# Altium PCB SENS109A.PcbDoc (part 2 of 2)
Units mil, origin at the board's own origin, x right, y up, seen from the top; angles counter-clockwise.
Board outline 2760 x 2518.85 mil, 4 copper layers (Top Layer, Signal Layer 1, Signal Layer 2, Bottom Layer), stack 62.2 mil thick; 49 components, 21 nets, 113 pads, 294 vias.
Unrouted connection lines stored in the file: 4.
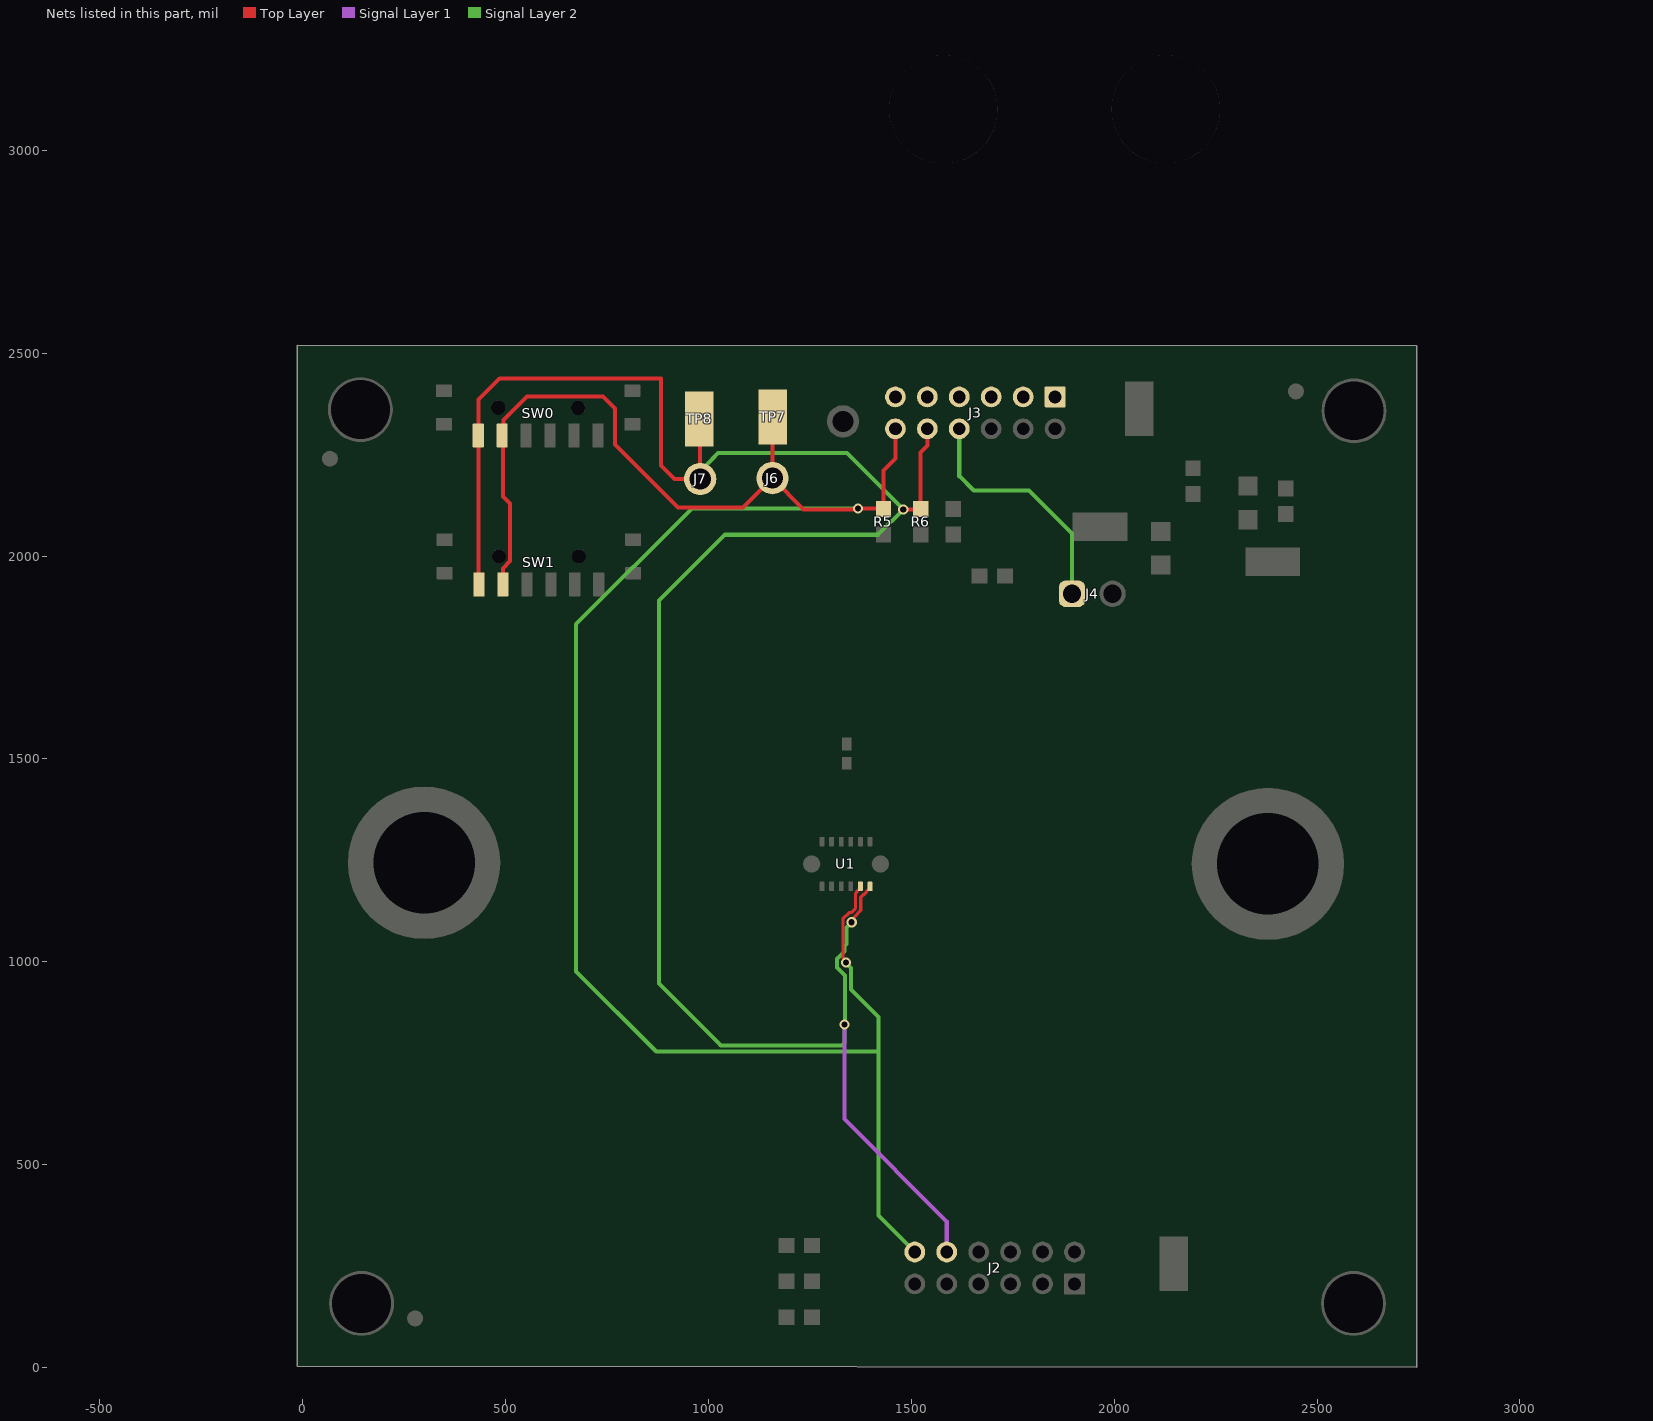
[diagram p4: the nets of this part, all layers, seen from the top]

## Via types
v1: diameter 25, hole 15, Top Layer to Bottom Layer, tented both sides, 193 vias
v2: diameter 18, hole 8, Top Layer to Bottom Layer, tented both sides, 97 vias
v3: diameter 25, hole 15, Top Layer to Bottom Layer, 4 vias

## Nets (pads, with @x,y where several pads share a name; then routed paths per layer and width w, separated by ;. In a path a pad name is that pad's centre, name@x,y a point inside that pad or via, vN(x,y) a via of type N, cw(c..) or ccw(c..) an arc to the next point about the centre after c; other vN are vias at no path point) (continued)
PD2_IN: J3.8 J4.1 | length 601.6
  Signal Layer 2 w10: J3.8@1618.18,2313.64 1618.18,2196.82 1653.88,2161.12 1790.31,2161.12 1896,2055.44 J4.1@1896,1907
PN4: J2.12 J3.12 J6.1 R5.1 SW0.5 SW1.5 TP7.1 U1.5 | length 5464.6
  Top Layer w8: v3(1339,998.12) 1339,1002.72 1331.5,1010.22 1331.5,1106.32 1346.54,1121.37 1351.54,1121.37 1362.62,1132.44 1362.62,1168.51 1365.72,1171.61 1365.72,1173.51 1370.4,1178.19 1372.53,1178.19 1373.53,1179.19 U1.5@1373.53,1185.1
  Top Layer w10: SW1.5@493,1929.69 SW1.5@493.42,1930.1 493.42,1969.65 511.29,1987.52 511.29,2129.11 493.42,2146.98 493.42,2295.1 SW0.5@491.42,2297.1 494.77,2300.46 494.77,2335.77 552.72,2393.72 740.28,2393.72 770,2364 770,2275 924.88,2120.12 1085.66,2120.12 J6.1@1157.66,2192.12 ; TP7.1@1158.66,2343.12 1157.66,2342.12 J6.1@1157.66,2192.12 ; U1.5@1373.53,1185.1 U1.5@1374.43,1186 ; R5.1@1431.17,2115.12 1429.17,2117.12 v1(1368.66,2117.12) 1366.66,2115.12 1234.66,2115.12 J6.1@1157.66,2192.12 ; R5.1@1431.17,2115.62 1431.17,2210.84 1441.36,2221.04 1460.66,2240.34 1460.66,2309.34 J3.12@1460.7,2309.38
  Signal Layer 2 w10: J6.1@1155.56,2190.02 J6.1@1157.66,2192.12 ; v3(1339,998.12) 1339,997.47 1351.7,984.77 1351.7,931.42 1372.25,910.87 1372.41,910.87 1419,864.29 1419,779.12 ; v1(1368.66,2117.12) 959.12,2117.12 674,1832 674,976.44 871.32,779.12 1419,779.12 ; J2.12@1508.52,284.74 1419,374.26 1419,779.12
PN5: J2.10 J3.10 J7.1 R6.1 SW0.6 SW1.6 TP8.1 U1.6 | length 5571.9
  Top Layer w8: v1(1353,1097.42) 1353,1102.02 1358.82,1107.83 1358.82,1110.25 1375.62,1127.06 1375.62,1159.48 1381.34,1165.19 1382.92,1165.19 1389.34,1171.61 1389.34,1173.19 1394.34,1178.19 1396.15,1178.19 1397.15,1179.19 U1.6@1397.15,1185.1
  Top Layer w10: SW1.6@433.36,1914.1 433.36,2386 485.51,2438.15 883,2438.15 883,2223 915.88,2190.12 J7.1@979.66,2190.12 979.66,2336.12 TP8.1@977.66,2338.12 977.66,2353.12 TP8.1@947.66,2383.12 ; U1.6@1397.15,1185.1 U1.6@1398.06,1186 ; v1(1480.17,2115.12) R6.1@1521.67,2115.12 ; R6.1@1523.17,2116.62 1522.17,2117.62 1522.17,2255.63 1539.44,2272.9 J3.10@1539.44,2313.64
  Signal Layer 1 w10: v3(1335,845) 1335,612.12 1587.26,359.86 J2.10@1587.26,284.74
  Signal Layer 2 w10: J7.1@979.66,2190.12 979.66,2208.94 1008.41,2237.69 1008.41,2238.68 1023.86,2254.12 1341.17,2254.12 v1(1480.17,2115.12) 1417.67,2052.63 1040.5,2052.63 878,1890.12 878,946.45 1030.33,794.12 1329.14,794.12 1335,799.98 v3(1335,845) ; v3@1336.7,846.7 1336.7,965.83 1316.5,986.03 1316.5,1007.44 1335,1025.94 1335,1038.92 1340.09,1044.01 1340.09,1084.06 1353,1096.97 v1(1353,1097.42)
PP0: J3.9
PP1: J3.11
PQ0: J3.3
PQ1: J3.1
PQ2: J3.5
PQ3: J3.7
pads on no net: FID1.1 FID2.1 FID3.1 H1.0 H2.0 H3.0 H4.0 H5.0 J2.1 J2.3 J2.5 J2.7 J2.9 J2.11 MP5. MP6. R745A.1 R745A.2 R745B.1 R745B.2 R746.1 R746.2 SW0. SW1.

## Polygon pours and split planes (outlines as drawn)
IS+ on Bottom Layer "BOTTOM_LAYER_IS+_P032" (solid, remove dead copper, pour order 32): 61,1820.12 1335,1820.12 1335,662.12 61,662.12
IS- on Bottom Layer "BOTTOM_LAYER_IS-_P034" (solid, remove dead copper, pour order 34): 1343,1820.12 2617,1820.12 2617,662.12 1343,662.12
IS- on Top Layer "TOP_LAYER_IS-_P028" (solid, remove dead copper, pour order 28): 1343,1820.12 2617,1820.12 2617,662.12 1343,662.12
GND on Top Layer "TOP_LAYER_GND_P030" (solid, remove dead copper, pour order 30): 1253.66,2478.12 1253.66,2161.12 2136.66,2161.12 2136.66,2478.12
IS+ on Top Layer "TOP_LAYER_IS+_P026" (solid, pour order 26): 61,1820.12 1335,1820.12 1335,662.12 61,662.12
IS+ on Signal Layer 1 "SIGNAL_LAYER_1_IS+_P036" (solid, remove dead copper, pour order 36): 61,1820.12 1335,1820.12 1335,662.12 61,662.12
IS- on Signal Layer 1 "SIGNAL_LAYER_1_IS-_P040" (solid, remove dead copper, pour order 40): 1343,1820.12 2617,1820.12 2617,662.12 1343,662.12
IS+ on Signal Layer 2 "SIGNAL_LAYER_2_IS+_P038" (solid, remove dead copper, pour order 38): 61,1820.12 1335,1820.12 1335,662.12 61,662.12
IS- on Signal Layer 2 "SIGNAL_LAYER_2_IS-_P044" (solid, remove dead copper, pour order 44): 1343,1820.12 2617,1820.12 2617,662.12 1343,662.12

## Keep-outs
Keep-Out Layer:
  text ".Layer_Name" at 263,-990.37 h60

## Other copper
Top Layer:
  text ".Layer_Name" at 263,-990.37 h60
Bottom Layer:
  text ".Layer_Name" at 263,-990.37 h60

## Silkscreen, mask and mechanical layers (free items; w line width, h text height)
Top Overlay:
  circle w8: c404,1590 r11.4
  circle w8: c2474,723 r11.4
  lines w10: 46,1835.12 118,1835.12 ; 47,681.62 47,748.62 ; 47,790.62 47,857.62 ; 47,899.62 47,966.62 ; 47,1007.62 47,1074.62 ; 47,1116.62 47,1183.62 ; 47,1225.62 47,1292.62 ; 47,1332.62 47,1399.62 ; 47,1441.62 47,1508.62 ; 47,1550.62 47,1617.62 ; 47,1658.62 47,1725.62 ; 47,1767.62 47,1834.62 ; 48,645.12 120,645.12 ; 156,1835.12 228,1835.12 ; 158,645.12 230,645.12 ; 264,1835.12 336,1835.12 ; 266,645.12 338,645.12 ; 348,350 1306,350 ; 374,1835.12 446,1835.12 ; 376,645.12 448,645.12 ; 483,1835.12 555,1835.12 ; 485,645.12 557,645.12 ; 593,1835.12 665,1835.12 ; 595,645.12 667,645.12 ; 705,1835.12 777,1835.12 ; 707,645.12 779,645.12 ; 815,1835.12 887,1835.12 ; 817,645.12 889,645.12 ; 826.5,72 826.5,442 ; 924,1835.12 996,1835.12 ; 926,645.12 998,645.12 ; 1034,1835.12 1106,1835.12 ; 1036,645.12 1108,645.12 ; 1138,72 1138,439 ; 1142,1835.12 1214,1835.12 ; 1144,645.12 1216,645.12 ; 1252,1835.12 1324,1835.12 ; 1254,645.12 1326,645.12 ; 1361,1835.12 1433,1835.12 ; 1363,645.12 1435,645.12 ; 1471,1835.12 1543,1835.12 ; 1473,645.12 1545,645.12 ; 1581,1835.12 1653,1835.12 ; 1583,645.12 1655,645.12 ; 1691,1835.12 1763,1835.12 ; 1693,645.12 1765,645.12 ; 1800,1835.12 1872,1835.12 ; 1802,645.12 1874,645.12 ; 1910,1835.12 1982,1835.12 ; 1912,645.12 1984,645.12 ; 2018,1835.12 2090,1835.12 ; 2020,645.12 2092,645.12 ; 2128,1835.12 2200,1835.12 ; 2130,645.12 2202,645.12 ; 2237,1835.12 2309,1835.12 ; 2239,645.12 2311,645.12 ; 2347,1835.12 2419,1835.12 ; 2349,645.12 2421,645.12 ; 2456,1835.12 2528,1835.12 ; 2458,645.12 2530,645.12 ; 2566,1835.12 2638,1835.12 ; 2568,645.12 2640,645.12 ; 2654,683.12 2654,750.12 ; 2654,792.12 2654,859.12 ; 2654,901.12 2654,968.12 ; 2654,1009.12 2654,1076.12 ; 2654,1118.12 2654,1185.12 ; 2654,1227.12 2654,1294.12 ; 2654,1334.12 2654,1401.12 ; 2654,1443.12 2654,1510.12 ; 2654,1552.12 2654,1619.12 ; 2654,1660.12 2654,1727.12 ; 2654,1769.12 2654,1836.12 ; 345,72 1308,72 1308,442 345,442 345,72
  text "A0" at 222,2256 h72.83
  text "NC" at 1761,2229.12 h20
  text "NC" at 1525,2228.12 h20
  text "NC" at 1603,2228.12 h20
  text "NC" at 1682,2228.12 h20
  text "NC" at 1839,2228.12 h20
  text "NC" at 1444,2227.12 h20
  text "SCL" at 1512.46,2193.8 h20
  text "SDA" at 1427.8,2193.12 h20
  text "3V3" at 1682,2192.1 h20
  text "GND" at 1754.32,2192.1 h20
  text "5V" at 1842.09,2192.53 h20
  text "SCL" at 462,2164 h30 r90
  text "PD2_IN" at 1568,2163.33 h20
  text "SDA" at 551.24,2160 h30 r90
  text "3V3" at 630,2160 h30 r90
  text "GND" at 704,2155 h30 r90
  text "A1" at 225.4,2007 h72.83
  text "PD2_IN" at 1815,1970.33 h20
  text "ALERT" at 1974,1968 h20
  text "40V MAX / 30A MAX" at 63,1589.23 h80
  text "at 105 C" at -23,1520 h50
  text "IS-" at 1941,1307 h40
  text "IS+" at 600,1122 h40
  text "40V MAX / 30A MAX" at 2089,718.23 h80
  text "at 105 C" at 2047,653 h50
  text "CAUTION HOT SURFACE" at -76,603 h120
  text "'.PRJ_Title' / .PRJ_Number.SCH_REV" at 162,488.95 h40
  text "U1" at 945,374 h72.83
  text "Y/N" at 1172,374 h72.83
  text "PCB Variant" at 392,373 h72.83
  text "SENS109_001" at 378,283 h72.83
  text "INA745A" at 857,278 h72.83
  text "SENS109_002" at 378,195 h72.83
  text "INA745B" at 857,186 h72.83
  text "SENS109_003" at 375,106 h72.83
  text "INA746" at 857,100 h72.83
  text ".Layer_Name" at 263,-990.37 h60
Bottom Overlay:
  lines w10: 44,1836 116,1836 ; 45,644.88 117,644.88 ; 45,682.5 45,749.5 ; 45,791.5 45,858.5 ; 45,900.5 45,967.5 ; 45,1008.5 45,1075.5 ; 45,1117.5 45,1184.5 ; 45,1226.5 45,1293.5 ; 45,1333.5 45,1400.5 ; 45,1442.5 45,1509.5 ; 45,1551.5 45,1618.5 ; 45,1659.5 45,1726.5 ; 45,1768.5 45,1835.5 ; 46,646 118,646 ; 154,1836 226,1836 ; 156,646 228,646 ; 262,1836 334,1836 ; 264,646 336,646 ; 372,1836 444,1836 ; 374,646 446,646 ; 481,1836 553,1836 ; 483,646 555,646 ; 591,1836 663,1836 ; 593,646 665,646 ; 703,1836 775,1836 ; 705,646 777,646 ; 813,1836 885,1836 ; 815,646 887,646 ; 922,1836 994,1836 ; 924,646 996,646 ; 1032,1836 1104,1836 ; 1034,646 1106,646 ; 1140,1836 1212,1836 ; 1142,646 1214,646 ; 1250,1836 1322,1836 ; 1252,646 1324,646 ; 1359,1836 1431,1836 ; 1361,646 1433,646 ; 1469,1836 1541,1836 ; 1471,646 1543,646 ; 1579,1836 1651,1836 ; 1581,646 1653,646 ; 1689,1836 1761,1836 ; 1691,646 1763,646 ; 1798,1836 1870,1836 ; 1800,646 1872,646 ; 1908,1836 1980,1836 ; 1910,646 1982,646 ; 2016,1836 2088,1836 ; 2018,646 2090,646 ; 2126,1836 2198,1836 ; 2128,646 2200,646 ; 2235,1836 2307,1836 ; 2237,646 2309,646 ; 2345,1836 2417,1836 ; 2347,646 2419,646 ; 2454,1836 2526,1836 ; 2456,646 2528,646 ; 2564,1836 2636,1836 ; 2566,646 2638,646 ; 2648,685 2648,752 ; 2648,794 2648,861 ; 2648,903 2648,970 ; 2648,1011 2648,1078 ; 2648,1120 2648,1187 ; 2648,1229 2648,1296 ; 2648,1336 2648,1403 ; 2648,1445 2648,1512 ; 2648,1554 2648,1621 ; 2648,1662 2648,1729 ; 2648,1771 2648,1838
  text "CAUTION HOT SURFACE" at 2535,599.88 h120
  text ".Layer_Name" at 263,-990.37 h60
Top Paste:
  text ".Layer_Name" at 263,-990.37 h60
Bottom Paste:
  text ".Layer_Name" at 263,-990.37 h60
Top Solder:
  text ".Layer_Name" at 263,-990.37 h60
  text ".Layer_Name" at 263,-990.37 h60
Bottom Solder:
  text ".Layer_Name" at 263,-990.37 h60
Drill Guide:
  text ".Layer_Name" at 263,-990.37 h60
M1 Board Outline:
  the board outline again, w10
  text ".Layer_Name" at 263,-990.37 h60
M2 Board Dimensions:
  rectangle: -367,-543.88 -242,-418.88
  rectangle: -242,-667.88 133,-542.88
  text ".Layer_Name" at 263,-990.37 h60
M3 3D STEP Top:
  text ".Layer_Name" at 263,-990.37 h60
M4 3D STEP Bottom:
  text ".Layer_Name" at 263,-990.37 h60
M5 Assembly Top:
  text "COMPONENTS MARKED 'DNP' SHOULD NOT BE POPULATED." at 863,-366.88 h60
  text "ASSEMBLY VARIANT:" at 839,-565.88 h60
  text ".VariantName" at 1875,-565.88 h60
  text "PCB VIEWED FROM TOP SIDE" at -542.5,-787.54 h60
  text "BOARD #:" at 1934,-787.54 h60
  text ".PRJ_Number" at 2479.5,-787.54 h60
  text "REV:" at 3324,-787.54 h60
  text ".PCB_Rev" at 3615.5,-787.54 h60
  text "SVN REV:" at 4162,-787.54 h60
  text ".VersionControl_RevNumber" at 4668,-787.54 h60
  text "TID #:" at 1934,-990.88 h60
  text ".TID" at 2479.5,-990.88 h60
  text "PLOT NAME =" at -542.5,-1196.21 h60
  text ".plot_File_Name" at 263,-1196.21 h60
  text "GENERATED    :" at 1936,-1196.21 h60
  text ".Print_Date" at 2805.5,-1196.21 h60
  text ".Print_Time" at 3534.5,-1196.21 h60
  text "TEXAS INSTRUMENTS" at 4799,-1196.21 h60
M6 Assembly Bottom:
  text "COMPONENTS MARKED 'DNP' SHOULD NOT BE POPULATED." at 5759,28.12 h60
  text ".VariantName" at 4744,-565.88 h60
  text "ASSEMBLY VARIANT:" at 5783,-565.88 h60
  text ".VersionControl_RevNumber" at 721.5,-788.04 h60
  text "SVN REV:" at 1227.5,-788.04 h60
  text ".PCB_Rev" at 1774,-788.04 h60
  text "REV:" at 2065.5,-788.04 h60
  text ".PRJ_Number" at 2910,-788.04 h60
  text "BOARD #:" at 3455.5,-788.04 h60
  text "PCB VIEWED FROM BOTTOM SIDE" at 5932,-788.04 h60
  text ".TID" at 2910,-991.38 h60
  text "TID #:" at 3455.5,-991.38 h60
  text "TEXAS INSTRUMENTS" at 590.5,-1196.71 h60
  text ".Print_Time" at 1855,-1196.71 h60
  text ".Print_Date" at 2584,-1196.71 h60
  text "GENERATED    :" at 3453.5,-1196.71 h60
  text ".plot_File_Name" at 5126.5,-1196.71 h60
  text "PLOT NAME =" at 5932,-1196.71 h60
M9 Title Sheet:
  drawing of 18 lines, arcs and shapes, not listed
  text "1" at 425.84,7904.62 h70
  text "2" at 2921.5,7904.62 h70
  text "3" at 5410.84,7904.62 h70
  text "4" at 7917.51,7904.62 h70
  text "5" at 10416.5,7904.62 h70
  text "6" at 12921.5,7904.62 h70
  text "A" at -730.5,6761.62 h70
  text "A" at 14069.5,6761.62 h70
  text "B" at -730.5,4381.62 h70
  text "B" at 14069.5,4381.62 h70
  text "C" at -730.5,2006.62 h70
  text "C" at 14069.5,2006.62 h70
  text "PROJECT TITLE:" at 11029.5,145.62 h45
  text ".PRJ_Title" at 11079.5,12.3 h70
  text "DESIGNED FOR:" at 11029.5,-155.38 h45
  text ".PRJ_Customer" at 11079.5,-295.38 h70
  text "D" at -730.5,-363.38 h70
  text "D" at 14069.5,-363.38 h70
  text "FILE NAME:" at 11029.5,-455.38 h45
  text ".PCB_File_Name_No_Path" at 11079.5,-575.38 h70
  text "Texas Instruments (TI) and/or its licensors do not warrant the accuracy or completeness of this specification" at 6060,-737.22 h45
  text "ENGINEER:" at 11029.5,-745.38 h45
  text "LAYOUT BY:" at 12534.5,-745.38 h45
  text "or any information contained therein. TI and/or its licensors do not warrant that this design will meet" at 6015.01,-849.88 h45
  text ".PRJ_Engineer" at 11079.5,-900.37 h70
  text ".PCB_Layout" at 12585,-900.37 h70
  text "the specifications, will be suitable for your application or fit for any particular purpose, or will operate in" at 6015.01,-962.55 h45
  text ".Layer_Name" at 263,-990.37 h60
  text "ALTIUM DESIGNER VERSION:" at 12534.5,-1055.38 h45
  text "an implementation. TI and/or its licensors do not warrant that the design is production worthy. You should" at 6015.01,-1075.21 h45
  text "completely validate and test your design implementation to confirm the system functionality for your application." at 6060,-1187.88 h45
  text ".print_Scale" at 11079.5,-1188.7 h70
  text ".Application_BuildNumber" at 12585,-1188.7 h70
  text "1" at 425.84,-1395.38 h70
  text "2" at 2921.5,-1395.38 h70
  text "3" at 5410.84,-1395.38 h70
  text "4" at 7917.51,-1395.38 h70
  text "5" at 10416.5,-1395.38 h70
  text "6" at 12921.5,-1395.38 h70
M10 Fab Notes:
  text "DESIGN INFORMATION" at 12068.02,6224.3 h60
  text "MIN. TRACK WIDTH:" at 11423.46,6092.17 h60
  text "8" at 12519.7,6092.17 h60
  text "MIL" at 12674.46,6092.17 h60
  text "mm" at 12798,5972.12 h60
  text "MIN. CLEARANCE:" at 11423.46,5968.04 h60
  text "0.127" at 12459.7,5968.05 h60
  text "MIN. VIA PAD SIZE:" at 11423.46,5843.92 h60
  text "18" at 12489.71,5843.92 h60
  text "MIL" at 12674.46,5843.92 h60
  text "5 MIL" at 12118.46,5714.02 h60
  text "MINIMUM ANNULAR RING" at 11094.23,5705.8 h60
  text "EXTERNAL" at 12826.46,5705.8 h60
  text "PER" at 11294.23,5595.67 h60
  text "IPC-D-275 CLASS 2 LEVEL C" at 11514.23,5595.67 h60
  text "MIL, HOLES" at 13002.46,5495.19 h60
  text "+/-" at 12610,5486.61 h60
  text "+/-" at 13464,5486.61 h60
  text "REGISTRATION TOLERANCES:" at 11094.23,5485.54 h60
  text "METAL" at 12294,5485.54 h60
  text "5" at 12870.2,5485.54 h60
  text "3" at 13703.2,5485.54 h60
  text "MIL" at 13819.46,5485.54 h60
  text "HOLE SIZE TOLERANCE (UNLESS OTHERWISE SPECIFIED):" at 11094.23,5387.23 h60
  text "+/-" at 13464,5384.35 h60
  text "3" at 13703.2,5383.29 h60
  text "MIL" at 13819.46,5383.29 h60
  text "MATERIAL:" at 11019.46,5245.64 h60
  text "FR-4 High Tg" at 12005.9,5117.12 h60
  text "X" at 11861.46,5109.13 h60
  text "FR-408" at 11440.46,5104.61 h60
  text "OTHER" at 12928.46,5104.61 h60
  text "63 MIL (1.6mm) +/-10%" at 11760.56,4961.58 h60
  text "X" at 11640.46,4959.13 h60
  text "THICKNESS:" at 11094.23,4953.36 h60
  text "OTHER" at 13045.46,4953.36 h60
  text "TOLERANCE:" at 11094.23,4815.05 h60
  text "X" at 11942.46,4815.05 h60
  text "ANSI IPC-6012 TYPE 3 CLASS 2" at 12120.48,4815.05 h60
  text "OTHER +/-" at 12120.46,4670.86 h60
  text "BOW & TWIST:" at 11094.23,4525.67 h60
  text "X" at 11942.46,4525.67 h60
  text "ANSI IPC-6012 TYPE 3 CLASS 2" at 12120.48,4525.67 h60
  text "OTHER +/-" at 12120.46,4378.97 h60
  text "DRILLING:" at 11019.46,4248.35 h60
  text "NC_DRILL FILES" at 12780.46,4143.16 h60
  text "REFERENCE:" at 11094.23,4139.23 h60
  text "X" at 11751.46,4139.13 h60
  text "AS SHOWN" at 11929.46,4139.23 h60
  text "X" at 12652.46,4139.23 h60
  text "OTHER" at 13078.46,3996.97 h60
  text "PTH COPPER THICKNESS:" at 11093.91,3993.45 h60
  text "X" at 12233.14,3993.45 h60
  text "20-30 um" at 12361.14,3993.45 h60
  text "BOARD FINISH:" at 11019.46,3845.85 h60
  text "SILKSCREEN:" at 11174.68,3735.72 h60
  text "X" at 12132.46,3735.72 h60
  text "TOP" at 12249.46,3735.72 h60
  text "X" at 12642.46,3735.72 h60
  text "BOTTOM" at 12760.46,3735.72 h60
  text "SILKSCREEN COLOR:" at 11174.68,3580.53 h60
  text "X" at 12131.46,3580.53 h60
  text "WHITE" at 12249.46,3580.53 h60
  text "OTHER" at 12760.46,3580.53 h60
  text "X" at 12262.46,3437.09 h60
  text "GREEN" at 12380.46,3437.09 h60
  text "OTHER" at 12998.46,3437.09 h60
  text "SOLDER RESIST COLOR:" at 11174.68,3430.22 h60
  text "X" at 12262.46,3282.83 h60
  text "MATTE" at 12380.46,3282.83 h60
  text "SEMI-GLOSS" at 12998,3282.2 h60
  text "IMMERSION GOLD (ENIG)" at 12080.46,3110.06 h60
  text "ENEPIG" at 13418,3102.84 h60
  text "SURFACE FINISH:" at 11019.46,3101.84 h60
  text "X" at 11902.46,3101.84 h60
  text "IMM. TIN/SILVER OR EQUIV" at 11349,2964.53 h60
  text "OTHER" at 12780.46,2960.59 h60
  text "ARRAY/PANEL:" at 11019.46,2805.21 h60
  text "CUT AND TRIM PER M1 BOARD OUTLINE" at 12080.46,2796.99 h60
  text "N.C. ROUTE" at 12080.46,2661.02 h60
  text "X" at 12768.46,2661.02 h60
  text "V. SCORE" at 12946.46,2661.02 h60
  text "CERTIFICATION:" at 11019.46,2531.9 h60
  text "MATERIALS AND WORKMANSHIP FOR ALL PCBS" at 11744.46,2531.9 h60
  text "TO MEET OR EXCEED THE REQUIREMENTS OF:" at 11744.46,2437.83 h60
  text "X" at 11381.97,2309.2 h60
  text "ANSI IPC-A-600F CLASS ->" at 11509.96,2309.2 h60
  text "X" at 13157.97,2309.2 h60
  text "2" at 13267.96,2309.2 h60
  text "1" at 12952.96,2307.71 h60
  text "3" at 13621.96,2307.71 h60
  text "X" at 12193.97,2161.52 h60
  text "RoHS" at 12321.96,2161.52 h60
  text "OTHER" at 12966.36,2161.52 h60
  text "PER ORDER" at 13363.42,2161.52 h60
  text "ALL BOARDS MUST MEET OR EXCEED UL94-V0 REQUIREMENTS." at 11047,2007.69 h60
  text "PCB MUST BEAR THE UL94V-0 UL REGISTERED MATERIAL ID NUMBER" at 11047,1891.63 h60
  text "ADDITIONAL REQUIREMENTS:" at 11019.46,1722.2 h60
  text "MICROSECTION:" at 11094.23,1615.08 h60
  text "NO" at 11999.96,1615.08 h60
  text "X" at 12307,1483.12 h60
  text "REQUIRED" at 12861.46,1470.74 h60
  text "BARE BOARD ELEC. TEST:" at 11094.23,1467.89 h60
  text "NONE" at 12399.96,1467.89 h60
  text "PER ORDER" at 13453.46,1467.89 h60
  text "No VIAS REQUIRE NON-CONDUCTIVE FILL AND PLANARIZE" at 11262.38,1262.94 h59
  text "No VIAS REQUIRE CONDUCTIVE FILL AND PLANARIZE" at 11270.38,1158.97 h60
  text "OUTER XX MIL TRACES REQUIRE 50 OHM SINGLE-ENDED IMPEDANCE" at 11269.39,995.58 h58
  text "LAYER 2 & 3 (INNER LAYERS) 17 MIL WIDE, XX MIL SPACE / TRACES REQUIRE 100 OHM DIFFERENTIAL IMPEDANCE" at 11223,653.12 h60 r0.3
  text ".Layer_Name" at 263,-990.37 h60
M11 Gerber Information:
  text "ALL ARTWORK VIEWED FROM TOP SIDE" at -542.5,-787.54 h60
  text "BOARD #:" at 1934,-787.54 h60
  text ".PRJ_Number" at 2479.5,-787.54 h60
  text "REV:" at 3324,-787.54 h60
  text ".PCB_Rev" at 3615.5,-787.54 h60
  text "SVN REV:" at 4162,-787.54 h60
  text ".VersionControl_RevNumber" at 4668,-787.54 h60
  text "LAYER NAME =" at -542.5,-990.37 h60
  text "TID #:" at 1934,-990.88 h60
  text ".TID" at 2479.5,-990.88 h60
  text "PLOT NAME =" at -542.5,-1196.21 h60
  text ".plot_File_Name" at 263,-1196.21 h60
  text "GENERATED    :" at 1936,-1196.21 h60
  text ".Print_Date" at 2805.5,-1196.21 h60
  text ".Print_Time" at 3534.5,-1196.21 h60
  text "TEXAS INSTRUMENTS" at 4799,-1196.21 h60
M12 Stackup:
  drawing of 444 lines, arcs and shapes, not listed
  text "Layer" at 6399.09,5234.71 h60
  text "Name" at 6809,5234.71 h60
  text "Material" at 7748.74,5234.71 h60
  text "Thickness" at 8608.51,5234.71 h60
  text "Constant" at 9258.34,5234.71 h60
  text "Board Layer Stack" at 9828.2,5234.71 h60
  text "Top Overlay" at 6809,5114.71 h60
  text "Top Solder" at 6809,4994.71 h60
  text "Solder Resist" at 7748.74,4994.71 h60
  text "0.40mil" at 8608.51,4994.71 h60
  text "3.5" at 9258.34,4994.71 h60
  text "1" at 6399.09,4874.71 h60
  text "Top Layer" at 6809,4874.71 h60
  text "2.80mil" at 8608.51,4874.71 h60
  text "Dielectric1" at 6809,4754.71 h60
  text "FR-4" at 7748.74,4754.71 h60
  text "17.00mil" at 8608.51,4754.71 h60
  text "4.2" at 9258.34,4754.71 h60
  text "2" at 6399.09,4634.71 h60
  text "Signal Layer 1" at 6809,4634.71 h60
  text "2.80mil" at 8608.51,4634.71 h60
  text "Dielectric 2" at 6809,4514.71 h60
  text "FR-4" at 7748.74,4514.71 h60
  text "17.00mil" at 8608.51,4514.71 h60
  text "4.2" at 9258.34,4514.71 h60
  text "3" at 6399.09,4394.71 h60
  text "Signal Layer 2" at 6809,4394.71 h60
  text "2.80mil" at 8608.51,4394.71 h60
  text "Dielectric 3" at 6809,4274.71 h60
  text "FR-4" at 7748.74,4274.71 h60
  text "17.00mil" at 8608.51,4274.71 h60
  text "4.2" at 9258.34,4274.71 h60
  text "4" at 6399.09,4154.71 h60
  text "Bottom Layer" at 6809,4154.71 h60
  text "2.80mil" at 8608.51,4154.71 h60
  text "Bottom Solder" at 6809,4034.71 h60
  text "Solder Resist" at 7748.74,4034.71 h60
  text "0.40mil" at 8608.51,4034.71 h60
  text "3.5" at 9258.34,4034.71 h60
  text "Bottom Overlay" at 6809,3914.71 h60
  text ".Layer_Name" at 263,-990.37 h60
M13 Component Bodies Top:
  text ".Layer_Name" at 263,-990.37 h60
M14 Component Bodies Bottom:
  text ".Layer_Name" at 263,-990.37 h60
M15 Courtyards Top:
  text ".Layer_Name" at 263,-990.37 h60
M16 Courtyards Bottom:
  text ".Layer_Name" at 263,-990.37 h60
Drill Drawing:
  circle w10: c3047.72,4015.29 r27.63
  lines w10: 3020.09,3241.74 3075.34,3241.74 3075.34,3296.99 3020.09,3296.99 3020.09,3241.74 ; 3020.09,3366.06 3047.72,3379.87 3075.34,3366.06 3061.53,3393.69 3075.34,3421.31 3047.72,3407.5 3020.09,3421.31 3033.9,3393.69 3020.09,3366.06 ; 3020.09,3504.19 3033.9,3504.19 3033.9,3490.38 3061.53,3490.38 3061.53,3504.19 3075.34,3504.19 3075.34,3531.82 3061.53,3531.82 3061.53,3545.63 3033.9,3545.63 3033.9,3531.82 3020.09,3531.82 3020.09,3504.19 ; 3020.09,3614.7 3075.34,3614.7 3075.34,3669.95 3020.09,3669.95 3020.09,3614.7 ; 3020.09,3766.65 3047.72,3739.02 3075.34,3766.65 3047.72,3794.27 3020.09,3766.65 ; 3020.09,3877.15 3033.9,3877.15 3047.72,3863.34 3061.53,3877.15 3075.34,3877.15 3061.53,3890.97 3075.34,3904.78 3061.53,3904.78 3047.72,3918.59 3033.9,3904.78 3020.09,3904.78 3033.9,3890.97 3020.09,3877.15 ; 3020.09,4167.23 3075.34,4167.23 3047.72,4111.98 3020.09,4167.23 ; 3020.09,4236.3 3020.09,4250.11 3033.9,4263.93 3020.09,4277.74 3020.09,4291.55 3033.9,4291.55 3047.72,4277.74 3061.53,4291.55 3075.34,4291.55 3075.34,4277.74 3061.53,4263.93 3075.34,4250.11 3075.34,4236.3 3061.53,4236.3 3047.72,4250.11 3033.9,4236.3 3020.09,4236.3 ; 3031.14,3252.79 3064.29,3252.79 3064.29,3285.94 3031.14,3285.94 3031.14,3252.79
  lines w12: 2970,3204.44 6127.36,3204.44 ; 2970,4323.32 6127.36,4323.32 ; 3307.86,3080.12 3307.86,4447.64 ; 3609.5,3080.12 3609.5,4447.64 ; 4202.3,3080.12 4202.3,4447.64 ; 4461.44,3080.12 4461.44,4447.64 ; 4836.6,3080.12 4836.6,4447.64 ; 5560.93,3080.12 5560.93,4447.64 ; 2970,3080.12 6127.36,3080.12 6127.36,4447.64 2970,4447.64 2970,3080.12
  text "Symbol" at 3044.59,4360.62 h72
  text "Count" at 3345.16,4360.62 h72
  text "Hole Size" at 3646.8,4360.62 h72
  text "Plated" at 4239.6,4360.62 h72
  text "Hole Type" at 4498.74,4360.62 h72
  text "Drill Layer Pair" at 4873.89,4360.62 h72
  text "Hole Tolerance" at 5598.22,4360.62 h72
  text "97" at 3345.16,4236.3 h60
  text "8.00mil (0.203mm)" at 3646.8,4236.3 h60
  text "PTH" at 4239.6,4236.3 h60
  text "Round" at 4498.74,4236.3 h60
  text "Top Layer - Bottom Layer" at 4873.89,4236.3 h60
  text "197" at 3345.16,4111.98 h60
  text "15.00mil (0.381mm)" at 3646.8,4111.98 h60
  text "PTH" at 4239.6,4111.98 h60
  text "Round" at 4498.74,4111.98 h60
  text "Top Layer - Bottom Layer" at 4873.89,4111.98 h60
  text "24" at 3345.16,3987.66 h60
  text "31.50mil (0.800mm)" at 3646.8,3987.66 h60
  text "PTH" at 4239.6,3987.66 h60
  text "Round" at 4498.74,3987.66 h60
  text "Top Layer - Bottom Layer" at 4873.89,3987.66 h60
  text "4" at 3345.16,3863.34 h60
  text "35.43mil (0.900mm)" at 3646.8,3863.34 h60
  text "NPTH" at 4239.6,3863.34 h60
  text "Round" at 4498.74,3863.34 h60
  text "Top Layer - Bottom Layer" at 4873.89,3863.34 h60
  text "2" at 3345.16,3739.02 h60
  text "45.28mil (1.150mm)" at 3646.8,3739.02 h60
  text "PTH" at 4239.6,3739.02 h60
  text "Round" at 4498.74,3739.02 h60
  text "Top Layer - Bottom Layer" at 4873.89,3739.02 h60
  text "3" at 3345.16,3614.7 h60
  text "51.97mil (1.320mm)" at 3646.8,3614.7 h60
  text "PTH" at 4239.6,3614.7 h60
  text "Round" at 4498.74,3614.7 h60
  text "Top Layer - Bottom Layer" at 4873.89,3614.7 h60
  text "4" at 3345.16,3490.38 h60
  text "145.00mil (3.683mm)" at 3646.8,3490.38 h60
  text "PTH" at 4239.6,3490.38 h60
  text "Round" at 4498.74,3490.38 h60
  text "Top Layer - Bottom Layer" at 4873.89,3490.38 h60
  text "2" at 3345.16,3366.06 h60
  text "250.00mil (6.350mm)" at 3646.8,3366.06 h60
  text "PTH" at 4239.6,3366.06 h60
  text "Round" at 4498.74,3366.06 h60
  text "Top Layer - Bottom Layer" at 4873.89,3366.06 h60
  text "2" at 3345.16,3241.74 h60
  text "267.00mil (6.782mm)" at 3646.8,3241.74 h60
  text "NPTH" at 4239.6,3241.74 h60
  text "Round" at 4498.74,3241.74 h60
  text "Top Layer - Bottom Layer" at 4873.89,3241.74 h60
  text "335 Total" at 3345.16,3117.42 h60
  text ".Layer_Name" at 263,-990.37 h60
M17 Embedded Cavity:
  text ".Layer_Name" at 263,-990.37 h60
M18 Embedded Assembly:
  text ".Layer_Name" at 263,-990.37 h60
M19 Embedded Keepout:
  text ".Layer_Name" at 263,-990.37 h60

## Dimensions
-14,2520 to 2746,2518.15 on M2 Board Dimensions
-14,3 to -14,2520 on M2 Board Dimensions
